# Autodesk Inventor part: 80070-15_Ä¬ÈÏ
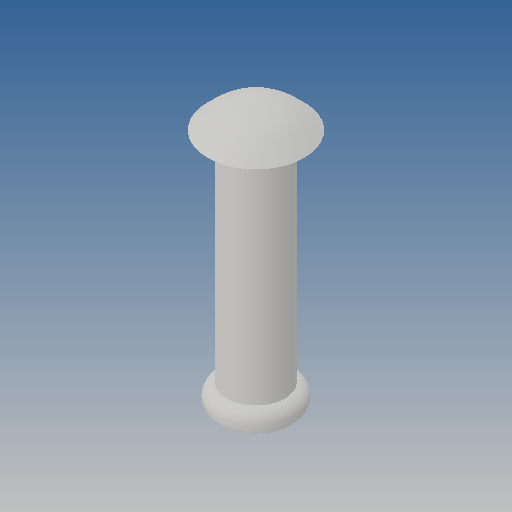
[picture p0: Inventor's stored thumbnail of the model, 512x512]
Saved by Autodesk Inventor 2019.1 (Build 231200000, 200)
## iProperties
Created: 2010-06
Part Number: 80070-15_Ä¬ÈÏ
Material: Ogólny
Document SubType Name: Modeling
Designer: CADENGINEERING4
Density: 1 g/cm^3
Appearance: Domyślna
Author: CADENGINEERING4
Revision Number: ÈÎºÎ
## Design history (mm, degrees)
feature "NONE"
node "Bryła1"
